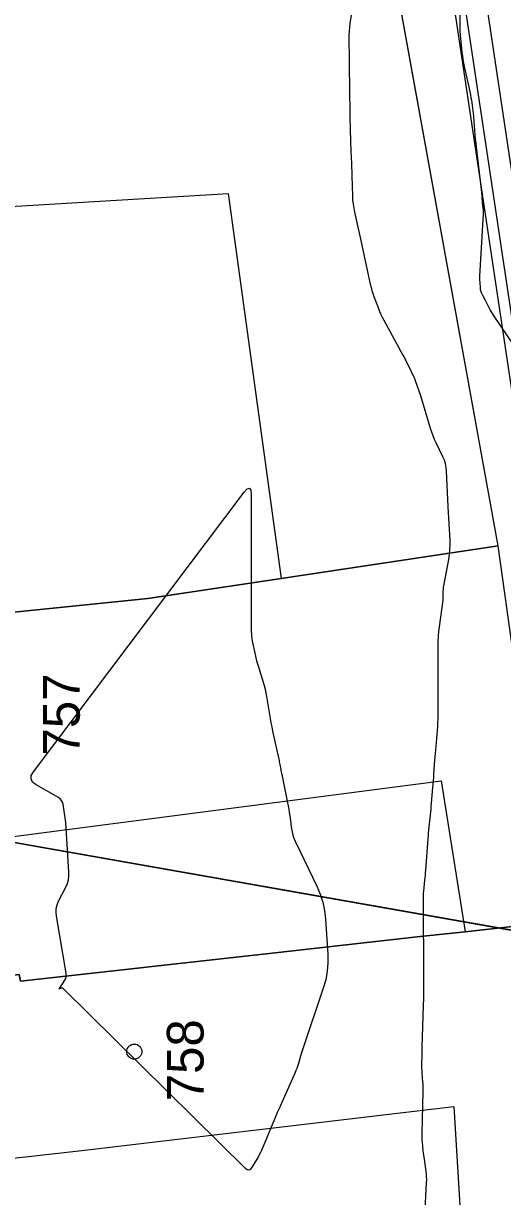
# Model space of a CAD drawing. Extents: x -534481 to -534256, y -1190577 to -1190138.
# Drawn here: x -534418.57 to -534407.48, y -1190463.81 to -1190436.66 of the extents above; entities that cross this region are included whole.
import ezdxf

# ---------------------------------------------------------------- set-up
doc = ezdxf.new("R2010")
doc.units = 0
for name, color, linetype in [('30', 7, 'Continuous'), ('31', 7, 'Continuous'), ('_N_osa', 7, 'Continuous'), ('_rámeček', 7, 'Continuous'), ('_tenka', 7, 'Continuous'), ('Hranice parcel', 7, 'Continuous'), ('Parcelní čísla', 7, 'Continuous'), ('Polygon budovy', 7, 'Continuous'), ('Značky budov', 7, 'Continuous')]:
    doc.layers.add(name, color=color, linetype=linetype)

msp = doc.modelspace()

# ---------------------------------------------------------------- linework, layer by layer
at = {"layer": '30'}
msp.add_lwpolyline([(-534410.922, -1190436.082), (-534411.012, -1190436.668), (-534411.024, -1190436.756), (-534411.032, -1190436.845), (-534411.036, -1190436.934), (-534411.037, -1190437.023), (-534411.031, -1190437.487), (-534411.028, -1190437.699), (-534411.022, -1190438.124), (-534411.021, -1190438.265), (-534411.015, -1190438.664), (-534411.014, -1190438.754), (-534411.012, -1190438.844), (-534411.01, -1190438.935), (-534411.007, -1190439.025), (-534410.994, -1190439.479), (-534410.992, -1190439.538), (-534410.99, -1190439.598), (-534410.987, -1190439.657), (-534410.985, -1190439.716), (-534410.975, -1190439.953), (-534410.973, -1190440.012), (-534410.97, -1190440.071), (-534410.968, -1190440.131), (-534410.966, -1190440.19), (-534410.953, -1190440.651), (-534410.948, -1190440.748), (-534410.938, -1190440.843), (-534410.924, -1190440.939), (-534410.905, -1190441.033), (-534410.731, -1190441.822), (-534410.727, -1190441.839), (-534410.72, -1190441.875), (-534410.539, -1190442.7), (-534410.522, -1190442.772), (-534410.502, -1190442.843), (-534410.48, -1190442.914), (-534410.455, -1190442.983), (-534410.35, -1190443.261), (-534410.323, -1190443.33), (-534410.293, -1190443.397), (-534410.261, -1190443.464), (-534410.227, -1190443.53), (-534409.782, -1190444.338), (-534409.763, -1190444.374), (-534409.744, -1190444.41), (-534409.726, -1190444.446), (-534409.708, -1190444.483), (-534409.619, -1190444.667), (-534409.61, -1190444.685), (-534409.601, -1190444.703), (-534409.593, -1190444.721), (-534409.584, -1190444.738), (-534409.549, -1190444.809), (-534409.54, -1190444.827), (-534409.532, -1190444.845), (-534409.524, -1190444.863), (-534409.517, -1190444.882), (-534409.435, -1190445.1), (-534409.419, -1190445.142), (-534409.404, -1190445.185), (-534409.39, -1190445.228), (-534409.377, -1190445.272), (-534409.151, -1190446.03), (-534409.124, -1190446.115), (-534409.093, -1190446.199), (-534409.059, -1190446.281), (-534409.022, -1190446.362), (-534408.866, -1190446.684), (-534408.831, -1190446.765), (-534408.805, -1190446.849), (-534408.788, -1190446.935), (-534408.78, -1190447.023), (-534408.74, -1190447.84), (-534408.74, -1190447.849), (-534408.699, -1190448.619), (-534408.696, -1190448.731), (-534408.701, -1190448.844), (-534408.711, -1190448.955), (-534408.729, -1190449.067), (-534408.844, -1190449.678), (-534408.849, -1190449.706), (-534408.852, -1190449.733), (-534408.854, -1190449.761), (-534408.855, -1190449.789), (-534408.855, -1190449.9), (-534408.855, -1190449.928), (-534408.857, -1190449.956), (-534408.859, -1190449.984), (-534408.862, -1190450.011), (-534408.946, -1190450.622), (-534408.959, -1190450.734), (-534408.969, -1190450.845), (-534408.974, -1190450.957), (-534408.976, -1190451.069), (-534408.976, -1190452.667), (-534408.977, -1190452.756), (-534408.98, -1190452.844), (-534408.985, -1190452.933), (-534408.992, -1190453.021), (-534409.023, -1190453.392), (-534409.03, -1190453.471), (-534409.037, -1190453.551), (-534409.043, -1190453.63), (-534409.049, -1190453.709), (-534409.072, -1190454.026), (-534409.078, -1190454.106), (-534409.084, -1190454.185), (-534409.09, -1190454.264), (-534409.097, -1190454.343), (-534409.127, -1190454.708), (-534409.133, -1190454.776), (-534409.14, -1190454.844), (-534409.146, -1190454.913), (-534409.153, -1190454.981), (-534409.182, -1190455.254), (-534409.189, -1190455.323), (-534409.195, -1190455.391), (-534409.201, -1190455.46), (-534409.207, -1190455.528), (-534409.261, -1190456.252), (-534409.265, -1190456.312), (-534409.27, -1190456.371), (-534409.276, -1190456.43), (-534409.281, -1190456.489), (-534409.306, -1190456.738), (-534409.311, -1190456.791), (-534409.314, -1190456.845), (-534409.316, -1190456.898), (-534409.316, -1190456.952), (-534409.315, -1190457.166), (-534409.315, -1190457.219), (-534409.315, -1190457.273), (-534409.314, -1190457.326), (-534409.314, -1190457.38), (-534409.306, -1190458.297), (-534409.305, -1190458.351), (-534409.305, -1190458.406), (-534409.304, -1190458.461), (-534409.304, -1190458.516), (-534409.303, -1190458.736), (-534409.303, -1190458.79), (-534409.303, -1190458.844), (-534409.304, -1190458.899), (-534409.304, -1190458.953), (-534409.308, -1190459.17), (-534409.309, -1190459.224), (-534409.31, -1190459.278), (-534409.311, -1190459.332), (-534409.313, -1190459.386), (-534409.343, -1190460.349), (-534409.345, -1190460.398), (-534409.346, -1190460.448), (-534409.347, -1190460.498), (-534409.348, -1190460.547), (-534409.351, -1190460.745), (-534409.352, -1190460.795), (-534409.351, -1190460.844), (-534409.348, -1190460.894), (-534409.345, -1190460.943), (-534409.327, -1190461.163), (-534409.324, -1190461.216), (-534409.321, -1190461.269), (-534409.321, -1190461.322), (-534409.321, -1190461.376), (-534409.346, -1190462.351), (-534409.347, -1190462.401), (-534409.346, -1190462.45), (-534409.343, -1190462.5), (-534409.339, -1190462.549), (-534409.319, -1190462.746), (-534409.313, -1190462.795), (-534409.308, -1190462.844), (-534409.301, -1190462.894), (-534409.294, -1190462.943), (-534409.254, -1190463.225), (-534409.246, -1190463.289), (-534409.242, -1190463.352), (-534409.24, -1190463.416), (-534409.242, -1190463.48), (-534409.282, -1190464.272)], dxfattribs=at)
at = {"layer": '31'}
msp.add_lwpolyline([(-534408.458, -1190436.275), (-534408.465, -1190436.68), (-534408.465, -1190436.762), (-534408.462, -1190436.844), (-534408.457, -1190436.926), (-534408.45, -1190437.008), (-534408.415, -1190437.336), (-534408.406, -1190437.417), (-534408.394, -1190437.499), (-534408.379, -1190437.58), (-534408.363, -1190437.66), (-534408.229, -1190438.269), (-534408.218, -1190438.326), (-534408.207, -1190438.384), (-534408.198, -1190438.441), (-534408.19, -1190438.498), (-534408.157, -1190438.751), (-534408.151, -1190438.798), (-534408.146, -1190438.845), (-534408.142, -1190438.892), (-534408.139, -1190438.939), (-534408.126, -1190439.127), (-534408.123, -1190439.174), (-534408.119, -1190439.221), (-534408.114, -1190439.268), (-534408.109, -1190439.315), (-534407.964, -1190440.576), (-534407.961, -1190440.603), (-534407.959, -1190440.629), (-534407.956, -1190440.656), (-534407.954, -1190440.683), (-534407.946, -1190440.799), (-534407.944, -1190440.822), (-534407.942, -1190440.844), (-534407.94, -1190440.867), (-534407.938, -1190440.89), (-534407.928, -1190440.98), (-534407.926, -1190441.002), (-534407.925, -1190441.025), (-534407.925, -1190441.047), (-534407.926, -1190441.07), (-534408.007, -1190442.51), (-534408.008, -1190442.543), (-534408.008, -1190442.577), (-534408.007, -1190442.61), (-534408.005, -1190442.644), (-534407.993, -1190442.799), (-534407.99, -1190442.821), (-534407.985, -1190442.843), (-534407.978, -1190442.865), (-534407.969, -1190442.886), (-534407.929, -1190442.969), (-534407.919, -1190442.989), (-534407.908, -1190443.01), (-534407.898, -1190443.03), (-534407.888, -1190443.051), (-534407.784, -1190443.255), (-534407.763, -1190443.296), (-534407.741, -1190443.335), (-534407.717, -1190443.374), (-534407.692, -1190443.413), (-534407.223, -1190444.108)], dxfattribs=at)
msp.add_lwpolyline([(-534417.819, -1190457.227), (-534417.813, -1190457.14), (-534417.792, -1190457.055), (-534417.758, -1190456.972), (-534417.591, -1190456.646), (-534417.555, -1190456.563), (-534417.531, -1190456.478), (-534417.519, -1190456.39), (-534417.519, -1190456.3), (-534417.594, -1190455.152), (-534417.598, -1190455.099), (-534417.604, -1190455.046), (-534417.611, -1190454.994), (-534417.619, -1190454.941), (-534417.655, -1190454.732), (-534417.669, -1190454.683), (-534417.692, -1190454.641), (-534417.724, -1190454.605), (-534417.765, -1190454.575), (-534418.281, -1190454.279), (-534418.361, -1190454.217), (-534418.398, -1190454.145), (-534418.392, -1190454.065), (-534418.343, -1190453.977), (-534413.461, -1190447.513), (-534413.389, -1190447.434), (-534413.337, -1190447.417), (-534413.305, -1190447.462), (-534413.295, -1190447.569), (-534413.295, -1190450.732), (-534413.294, -1190450.788), (-534413.289, -1190450.844), (-534413.282, -1190450.899), (-534413.272, -1190450.954), (-534413.206, -1190451.269), (-534413.19, -1190451.34), (-534413.173, -1190451.41), (-534413.154, -1190451.48), (-534413.132, -1190451.549), (-534413.019, -1190451.904), (-534412.994, -1190451.986), (-534412.973, -1190452.069), (-534412.955, -1190452.153), (-534412.94, -1190452.238), (-534412.875, -1190452.65), (-534412.858, -1190452.747), (-534412.841, -1190452.844), (-534412.822, -1190452.94), (-534412.802, -1190453.037), (-534412.659, -1190453.688), (-534412.652, -1190453.718), (-534412.646, -1190453.747), (-534412.64, -1190453.777), (-534412.635, -1190453.807), (-534412.613, -1190453.926), (-534412.608, -1190453.956), (-534412.602, -1190453.985), (-534412.596, -1190454.015), (-534412.59, -1190454.045), (-534412.455, -1190454.696), (-534412.441, -1190454.77), (-534412.427, -1190454.845), (-534412.415, -1190454.92), (-534412.405, -1190454.995), (-534412.365, -1190455.296), (-534412.352, -1190455.37), (-534412.333, -1190455.443), (-534412.309, -1190455.514), (-534412.279, -1190455.583), (-534411.777, -1190456.622), (-534411.699, -1190456.807), (-534411.639, -1190456.996), (-534411.598, -1190457.19), (-534411.576, -1190457.389), (-534411.524, -1190458.196), (-534411.521, -1190458.396), (-534411.537, -1190458.594), (-534411.572, -1190458.79), (-534411.627, -1190458.982), (-534412.095, -1190460.365), (-534412.111, -1190460.413), (-534412.126, -1190460.461), (-534412.141, -1190460.508), (-534412.155, -1190460.556), (-534412.211, -1190460.748), (-534412.226, -1190460.796), (-534412.242, -1190460.843), (-534412.26, -1190460.89), (-534412.28, -1190460.936), (-534412.618, -1190461.699), (-534412.626, -1190461.717), (-534412.635, -1190461.736), (-534412.643, -1190461.755), (-534412.652, -1190461.773), (-534412.686, -1190461.848), (-534412.694, -1190461.866), (-534412.702, -1190461.885), (-534412.711, -1190461.904), (-534412.719, -1190461.923), (-534413.062, -1190462.738), (-534413.086, -1190462.791), (-534413.111, -1190462.843), (-534413.139, -1190462.893), (-534413.168, -1190462.943), (-534413.289, -1190463.14), (-534413.32, -1190463.178), (-534413.354, -1190463.194), (-534413.391, -1190463.187), (-534413.431, -1190463.158), (-534417.66, -1190458.988), (-534417.668, -1190458.982), (-534417.675, -1190458.98), (-534417.684, -1190458.98), (-534417.693, -1190458.984), (-534417.728, -1190459.004), (-534417.735, -1190459.007), (-534417.739, -1190459.007), (-534417.739, -1190459.003), (-534417.736, -1190458.996), (-534417.613, -1190458.797), (-534417.595, -1190458.76), (-534417.584, -1190458.722), (-534417.58, -1190458.683), (-534417.583, -1190458.642), (-534417.81, -1190457.316)], close=True, dxfattribs=at)
at = {"layer": '_N_osa'}
msp.add_lwpolyline([(-534408.105, -1190518.46), (-534393.616, -1190502.389), (-534391.346, -1190496.962), (-534392.763, -1190488.017), (-534396.655, -1190477.752), (-534402.513, -1190464.283), (-534404.757, -1190456.741), (-534408.311, -1190433.088), (-534409.248, -1190427.879), (-534409.316, -1190416.054), (-534409.076, -1190409.418), (-534409.868, -1190391.439)], dxfattribs=at)
at = {"layer": '_rámeček'}
msp.add_line((-534316.367, -1190473.675), (-534462.611, -1190447.888), dxfattribs=at)
msp.add_lwpolyline([(-534298.134, -1190370.27), (-534444.378, -1190344.484), (-534462.611, -1190447.888), (-534316.367, -1190473.675)], dxfattribs=at)
at = {"layer": '_tenka'}
for points in [[(-534405.407, -1190514.348), (-534394.258, -1190501.982), (-534392.12, -1190496.869), (-534393.492, -1190488.211), (-534397.35, -1190478.035), (-534403.219, -1190464.54), (-534405.491, -1190456.905), (-534409.051, -1190433.21), (-534409.998, -1190427.948), (-534410.066, -1190416.042), (-534409.827, -1190409.421), (-534410.645, -1190390.84)], [(-534405.057, -1190514.333), (-534394.044, -1190502.118), (-534391.862, -1190496.9), (-534393.249, -1190488.146), (-534397.118, -1190477.94), (-534402.983, -1190464.455), (-534405.247, -1190456.85), (-534408.804, -1190433.17), (-534409.748, -1190427.925), (-534409.816, -1190416.046), (-534409.577, -1190409.42), (-534410.397, -1190390.795)]]:
    msp.add_lwpolyline(points, dxfattribs=at)
at = {"layer": 'Hranice parcel'}
for p, q in [((-534407.58, -1190448.75), (-534410.31, -1190433.69)), ((-534406.36, -1190457.46), (-534407.58, -1190448.75))]:
    msp.add_line(p, q, dxfattribs=at)
for points in [[(-534430.23, -1190451.45), (-534422.73, -1190450.69), (-534415.69, -1190449.97), (-534412.6, -1190449.51), (-534407.58, -1190448.75)], [(-534428.92, -1190459.94), (-534423.88, -1190459.32), (-534418.67, -1190458.67), (-534418.64, -1190458.82), (-534412.88, -1190458.18), (-534409.38, -1190457.79), (-534408.34, -1190457.68), (-534406.36, -1190457.46)]]:
    msp.add_lwpolyline(points, dxfattribs=at)
at = {"layer": 'Polygon budovy'}
for points in [[(-534422.89, -1190441.14), (-534413.83, -1190440.6), (-534412.6, -1190449.51), (-534407.58, -1190448.75), (-534410.31, -1190433.69), (-534414.28, -1190433.9), (-534430.98, -1190434.78), (-534430.23, -1190451.45), (-534422.73, -1190450.69), (-534422.94, -1190447.02), (-534422.61, -1190447)], [(-534430.23, -1190451.45), (-534428.92, -1190459.94), (-534423.88, -1190459.32), (-534424.22, -1190456.18), (-534408.9, -1190454.19), (-534408.34, -1190457.68), (-534406.36, -1190457.46), (-534407.58, -1190448.75), (-534412.6, -1190449.51), (-534415.69, -1190449.97), (-534422.73, -1190450.69)], [(-534428.92, -1190459.94), (-534427.58, -1190468.08), (-534423.54, -1190467.58), (-534422.92, -1190467.48), (-534423.48, -1190463.44), (-534417.22, -1190462.74), (-534408.6, -1190461.72), (-534408.43, -1190464.65), (-534409.02, -1190464.79), (-534408.85, -1190466.06), (-534403.85, -1190465.4), (-534406.36, -1190457.46), (-534408.34, -1190457.68), (-534409.38, -1190457.79), (-534412.88, -1190458.18), (-534418.64, -1190458.82), (-534418.67, -1190458.67), (-534423.88, -1190459.32)]]:
    msp.add_lwpolyline(points, close=True, dxfattribs=at)
at = {"layer": 'Značky budov'}
msp.add_circle((-534416.006, -1190460.454), 0.175, dxfattribs=at)

# ---------------------------------------------------------------- texts
at = {"layer": 'Parcelní čísla'}
for s, p in [('757', (-534417.27, -1190453.603)), ('758', (-534414.401, -1190461.602))]:
    msp.add_text(s, height=0.85, rotation=90, dxfattribs=at).set_placement(p)

doc.saveas('drawing.dxf')
